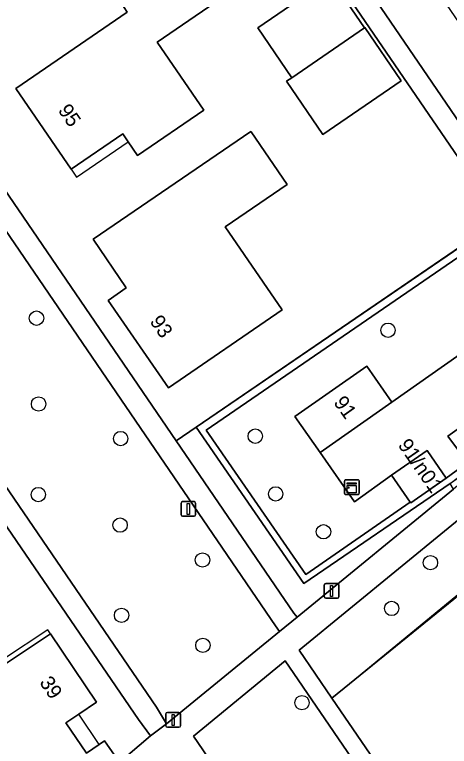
# Model space of a CAD drawing. Extents: x 155275 to 156265, y 382654 to 383635.
# Drawn here: x 155592.03 to 155621.62, y 383140.81 to 383190.6 of the extents above; entities that cross this region are included whole.
import ezdxf

# ---------------------------------------------------------------- set-up
doc = ezdxf.new("R2010")
doc.units = 0
for name, color, linetype in [('IMGEO_Boom', 7, 'Continuous'), ('IMGEO_Erf', 7, 'Continuous'), ('IMGEO_Groenvoorziening', 7, 'Continuous'), ('IMGEO_Haag', 7, 'Continuous'), ('IMGEO_Hek', 7, 'Continuous'), ('IMGEO_Kast', 7, 'Continuous'), ('IMGEO_Lichtmast', 7, 'Continuous'), ('IMGEO_Pand', 7, 'Continuous'), ('IMGEO_Pand_nummerreeks', 7, 'Continuous'), ('IMGEO_Pand_overbouw', 7, 'Continuous'), ('IMGEO_Rijbaan_lokaal_open', 7, 'Continuous'), ('IMGEO_Voetpad_open', 7, 'Continuous')]:
    doc.layers.add(name, color=color, linetype=linetype)

msp = doc.modelspace()

# ---------------------------------------------------------------- linework, layer by layer
at = {"layer": 'IMGEO_Boom'}
for centre in [(155593.514, 383169.945), (155617.44, 383169.125), (155593.657, 383164.102), (155599.241, 383161.753), (155608.404, 383161.915), (155593.639, 383157.942), (155609.791, 383157.985), (155599.204, 383155.861), (155613.048, 383155.409), (155604.814, 383153.491), (155620.327, 383153.305), (155617.688, 383150.19), (155599.304, 383149.723), (155604.839, 383147.683), (155611.585, 383143.777)]:
    msp.add_circle(centre, 0.489, dxfattribs=at)
at = {"layer": 'IMGEO_Erf'}
for points in [[(155583.923, 383230.311), (155564.944, 383217.349), (155603.025, 383161.596), (155604.389, 383162.527), (155625.107, 383176.674), (155589.111, 383229.212)], [(155599.73, 383140.197), (155601.267, 383141.518), (155600.446, 383142.636), (155554.33, 383210.1), (155526.983, 383191.422)], [(155677.255, 383131.208), (155648.848, 383172.815), (155635.334, 383161.916), (155632.001, 383158.991), (155630.588, 383157.845), (155613.622, 383144.086), (155622.569, 383130.992)]]:
    msp.add_lwpolyline(points, dxfattribs=at)
for points in [[(155601.727, 383188.737), (155604.906, 383184.1), (155600.389, 383181.011), (155599.761, 383181.944), (155599.389, 383182.497), (155595.866, 383180.083), (155592.109, 383185.575), (155599.692, 383190.774), (155599.266, 383191.396), (155605.382, 383195.589), (155607.409, 383192.632)], [(155610.896, 383186.311), (155608.57, 383189.699), (155613.515, 383193.095), (155615.842, 383189.707), (155615.858, 383189.718), (155618.338, 383186.106), (155613.01, 383182.447), (155610.537, 383186.064)], [(155608.133, 383182.62), (155610.584, 383179.034), (155606.367, 383176.168), (155610.233, 383170.502), (155602.488, 383165.198), (155598.386, 383171.136), (155599.624, 383172.006), (155597.375, 383175.316), (155608.092, 383182.645)], [(155591.263, 383146.732), (155591.465, 383146.457), (155594.469, 383148.456), (155597.599, 383143.82), (155596.391, 383143.004), (155595.513, 383142.412), (155596.908, 383140.347), (155597.78, 383140.94), (155598.14, 383141.184), (155599.133, 383139.755), (155585.977, 383129.245), (155582.75, 383133.961), (155588.627, 383137.901), (155585.357, 383142.772)]]:
    msp.add_lwpolyline(points, close=True, dxfattribs=at)
at = {"layer": 'IMGEO_Groenvoorziening'}
for points in [[(155590.692, 383176.929), (155582.623, 383171.362), (155601.671, 383143.463), (155602.361, 383142.34), (155610.043, 383148.625), (155609.791, 383149.013)], [(155605.072, 383162.322), (155624.938, 383175.959), (155627.871, 383171.732), (155628.287, 383172.031), (155625.107, 383176.674), (155604.389, 383162.527), (155611.707, 383151.893), (155621.66, 383158.683), (155623.094, 383159.792), (155631.833, 383166.856), (155631.606, 383167.187), (155622.856, 383160.114), (155621.409, 383159.063), (155618.987, 383157.375), (155618.959, 383157.415), (155611.84, 383152.49)], [(155628.453, 383171.789), (155628.287, 383172.031), (155627.871, 383171.732), (155624.938, 383175.959), (155605.072, 383162.322), (155611.84, 383152.49), (155618.959, 383157.415), (155617.677, 383159.258), (155615.157, 383157.441), (155612.814, 383160.802), (155611.101, 383163.245), (155615.989, 383166.673), (155617.702, 383164.23)], [(155631.606, 383167.187), (155631.067, 383167.974), (155630.734, 383168.461), (155621.518, 383161.922), (155622.856, 383160.114)], [(155621.904, 383158.314), (155621.66, 383158.683), (155611.707, 383151.893), (155604.389, 383162.527), (155603.025, 383161.596), (155611.034, 383149.871), (155611.256, 383149.591)], [(155630.588, 383157.845), (155628.302, 383161.197), (155611.386, 383147.359), (155613.622, 383144.086)], [(155610.441, 383146.625), (155604.19, 383141.494), (155614.913, 383125.805), (155621.572, 383130.348)]]:
    msp.add_lwpolyline(points, close=True, dxfattribs=at)
at = {"layer": 'IMGEO_Haag'}
msp.add_lwpolyline([(155625.107, 383176.674), (155604.389, 383162.527), (155611.707, 383151.893), (155621.66, 383158.683), (155623.094, 383159.792), (155631.833, 383166.856), (155631.606, 383167.187), (155622.856, 383160.114), (155621.409, 383159.063), (155618.987, 383157.375), (155618.959, 383157.415), (155611.84, 383152.49), (155605.072, 383162.322), (155624.938, 383175.959), (155627.871, 383171.732), (155628.287, 383172.031)], close=True, dxfattribs=at)
at = {"layer": 'IMGEO_Hek'}
for points in [[(155631.829, 383166.862), (155631.667, 383166.724), (155624.502, 383160.621), (155623.258, 383159.772), (155621.623, 383158.657), (155611.707, 383151.893), (155604.52, 383162.337), (155604.388, 383162.528), (155624.746, 383176.428), (155625.069, 383176.648)], [(155635.334, 383161.916), (155613.885, 383144.299), (155613.623, 383144.084)]]:
    msp.add_lwpolyline(points, dxfattribs=at)
at = {"layer": 'IMGEO_Kast'}
for p, q in [((155614.473, 383158.019), (155614.473, 383158.86)), ((155614.473, 383158.86), (155614.473, 383158.019)), ((155614.548, 383158.944), (155615.389, 383158.944)), ((155615.389, 383158.944), (155614.548, 383158.944)), ((155615.473, 383158.869), (155615.473, 383158.028)), ((155615.473, 383158.028), (155615.473, 383158.869)), ((155615.398, 383157.944), (155614.557, 383157.944)), ((155614.557, 383157.944), (155615.398, 383157.944))]:
    msp.add_line(p, q, dxfattribs=at)
for points in [[(155614.668, 383158.734), (155615.268, 383158.734), (155615.268, 383158.649), (155614.668, 383158.649), (155614.668, 383158.734)], [(155614.668, 383158.559), (155615.268, 383158.559), (155615.268, 383158.07), (155614.668, 383158.07), (155614.668, 383158.559)]]:
    msp.add_lwpolyline(points, dxfattribs=at)
msp.add_circle((155614.752, 383158.408), 0.0377, dxfattribs=at)
for centre, start, end in [((155614.551, 383158.866), 92.4484, 184.2845), ((155614.551, 383158.866), 92.4484, 184.2845), ((155615.395, 383158.866), 2.4484, 94.2845), ((155615.395, 383158.866), 2.4484, 94.2845), ((155614.551, 383158.022), 182.4484, 274.2845), ((155614.551, 383158.022), 182.4484, 274.2845), ((155615.395, 383158.022), 272.4484, 4.2845), ((155615.395, 383158.022), 272.4484, 4.2845)]:
    msp.add_arc(centre, 0.0779, start, end, dxfattribs=at)
at = {"layer": 'IMGEO_Lichtmast'}
for p, q in [((155603.351, 383156.562), (155603.351, 383157.362)), ((155603.351, 383157.362), (155603.351, 383156.562)), ((155603.451, 383157.462), (155604.241, 383157.462)), ((155604.241, 383157.462), (155603.451, 383157.462)), ((155604.341, 383157.362), (155604.341, 383156.562)), ((155604.341, 383156.562), (155604.341, 383157.362)), ((155604.241, 383156.462), (155603.451, 383156.462)), ((155603.451, 383156.462), (155604.241, 383156.462)), ((155613.101, 383150.987), (155613.101, 383151.787)), ((155613.101, 383151.787), (155613.101, 383150.987)), ((155613.201, 383151.887), (155613.991, 383151.887)), ((155613.991, 383151.887), (155613.201, 383151.887)), ((155614.091, 383151.787), (155614.091, 383150.987)), ((155614.091, 383150.987), (155614.091, 383151.787)), ((155613.991, 383150.887), (155613.201, 383150.887)), ((155613.201, 383150.887), (155613.991, 383150.887)), ((155602.321, 383142.209), (155602.321, 383143.009)), ((155602.321, 383143.009), (155602.321, 383142.209)), ((155602.421, 383143.109), (155603.211, 383143.109)), ((155603.211, 383143.109), (155602.421, 383143.109)), ((155603.311, 383143.009), (155603.311, 383142.209)), ((155603.311, 383142.209), (155603.311, 383143.009)), ((155603.211, 383142.109), (155602.421, 383142.109)), ((155602.421, 383142.109), (155603.211, 383142.109))]:
    msp.add_line(p, q, dxfattribs=at)
for points in [[(155603.771, 383157.337), (155603.921, 383157.337), (155603.921, 383156.587), (155603.771, 383156.587), (155603.771, 383157.337)], [(155613.521, 383151.762), (155613.671, 383151.762), (155613.671, 383151.012), (155613.521, 383151.012), (155613.521, 383151.762)], [(155602.741, 383142.984), (155602.891, 383142.984), (155602.891, 383142.234), (155602.741, 383142.234), (155602.741, 383142.984)]]:
    msp.add_lwpolyline(points, dxfattribs=at)
for centre, start, end in [((155603.451, 383157.362), 90, 180), ((155603.451, 383157.362), 90, 180), ((155604.241, 383157.362), 0, 90), ((155604.241, 383157.362), 360, 90), ((155603.451, 383156.562), 180, 270), ((155603.451, 383156.562), 180, 270), ((155604.241, 383156.562), 270, 0), ((155604.241, 383156.562), 270, 0), ((155613.201, 383151.787), 90, 180), ((155613.201, 383151.787), 90, 180), ((155613.991, 383151.787), 0, 90), ((155613.991, 383151.787), 360, 90), ((155613.201, 383150.987), 180, 270), ((155613.201, 383150.987), 180, 270), ((155613.991, 383150.987), 270, 0), ((155613.991, 383150.987), 270, 0), ((155602.421, 383143.009), 90, 180), ((155602.421, 383143.009), 90, 180), ((155603.211, 383143.009), 0, 90), ((155603.211, 383143.009), 360, 90), ((155602.421, 383142.209), 180, 270), ((155602.421, 383142.209), 180, 270), ((155603.211, 383142.209), 270, 0), ((155603.211, 383142.209), 270, 0)]:
    msp.add_arc(centre, 0.1, start, end, dxfattribs=at)
at = {"layer": 'IMGEO_Pand'}
for points in [[(155601.727, 383188.737), (155607.409, 383192.632), (155605.382, 383195.589), (155599.266, 383191.396), (155599.692, 383190.774), (155592.109, 383185.575), (155595.866, 383180.083), (155599.389, 383182.497), (155599.761, 383181.944), (155600.389, 383181.011), (155604.906, 383184.1)], [(155615.842, 383189.707), (155613.515, 383193.095), (155608.57, 383189.699), (155610.896, 383186.311)], [(155615.858, 383189.718), (155615.842, 383189.707), (155610.896, 383186.311), (155610.537, 383186.064), (155613.01, 383182.447), (155618.338, 383186.106)], [(155608.133, 383182.62), (155608.092, 383182.645), (155597.375, 383175.316), (155599.624, 383172.006), (155598.386, 383171.136), (155602.488, 383165.198), (155610.233, 383170.502), (155606.367, 383176.168), (155610.584, 383179.034)], [(155612.814, 383160.802), (155617.702, 383164.23), (155615.989, 383166.673), (155611.101, 383163.245)], [(155620.098, 383160.943), (155617.677, 383159.258), (155618.959, 383157.415), (155618.987, 383157.375), (155621.409, 383159.063)], [(155595.513, 383142.412), (155596.391, 383143.004), (155597.599, 383143.82), (155594.469, 383148.456), (155591.465, 383146.457), (155591.263, 383146.732), (155585.357, 383142.772), (155588.627, 383137.901), (155582.75, 383133.961), (155585.977, 383129.245), (155599.133, 383139.755), (155598.14, 383141.184), (155597.78, 383140.94), (155596.908, 383140.347)]]:
    msp.add_lwpolyline(points, close=True, dxfattribs=at)
at = {"layer": 'IMGEO_Pand_overbouw'}
for points in [[(155596.24, 383179.535), (155599.761, 383181.944), (155599.389, 383182.497), (155595.866, 383180.083)], [(155591.263, 383146.732), (155591.465, 383146.457), (155594.469, 383148.456), (155594.275, 383148.743)], [(155596.391, 383143.004), (155595.513, 383142.412), (155596.908, 383140.347), (155597.78, 383140.94)]]:
    msp.add_lwpolyline(points, close=True, dxfattribs=at)
at = {"layer": 'IMGEO_Rijbaan_lokaal_open'}
msp.add_lwpolyline([(155589.707, 383230.961), (155631.867, 383169.258), (155634.823, 383171.29), (155635.04, 383171.44), (155592.812, 383233.101)], dxfattribs=at)
at = {"layer": 'IMGEO_Voetpad_open'}
for points in [[(155589.111, 383229.212), (155625.107, 383176.674), (155628.287, 383172.031), (155628.453, 383171.789), (155630.734, 383168.461), (155631.867, 383169.258), (155589.707, 383230.961)], [(155622.569, 383130.992), (155613.622, 383144.086), (155611.386, 383147.359), (155628.302, 383161.197), (155630.588, 383157.845), (155632.001, 383158.991), (155629.709, 383162.347), (155633.075, 383165.119), (155632.007, 383166.602), (155631.041, 383165.794), (155623.326, 383159.478), (155621.904, 383158.314), (155611.256, 383149.591), (155610.043, 383148.625), (155602.361, 383142.34), (155601.267, 383141.518), (155599.73, 383140.197)]]:
    msp.add_lwpolyline(points, dxfattribs=at)
for points in [[(155590.692, 383176.929), (155609.791, 383149.013), (155610.043, 383148.625), (155611.256, 383149.591), (155611.034, 383149.871), (155603.025, 383161.596), (155564.944, 383217.349), (155563.71, 383216.506), (155585.619, 383184.371), (155589.29, 383178.983), (155581.203, 383173.388), (155577.49, 383178.854), (155555.557, 383210.938), (155554.33, 383210.1), (155600.446, 383142.636), (155601.267, 383141.518), (155602.361, 383142.34), (155601.671, 383143.463), (155582.623, 383171.362)], [(155630.734, 383168.461), (155628.453, 383171.789), (155617.702, 383164.23), (155612.814, 383160.802), (155615.157, 383157.441), (155617.677, 383159.258), (155620.098, 383160.943), (155621.409, 383159.063), (155622.856, 383160.114), (155621.518, 383161.922)], [(155604.19, 383141.494), (155610.441, 383146.625), (155621.572, 383130.348), (155614.913, 383125.805)]]:
    msp.add_lwpolyline(points, close=True, dxfattribs=at)

# ---------------------------------------------------------------- texts
at = {"layer": 'IMGEO_Pand_nummerreeks'}
for s, rotation, p in [('95', 304.3773, (155594.944, 383184.088)), ('93', 304.4403, (155601.189, 383169.722)), ('91', 305.6491, (155613.696, 383164.203)), ('91/n01', 304.8242, (155618.079, 383161.307)), ('39', 304.0278, (155593.679, 383145.159))]:
    msp.add_text(s, height=1, rotation=rotation, dxfattribs=at).set_placement(p)

doc.saveas('drawing.dxf')
